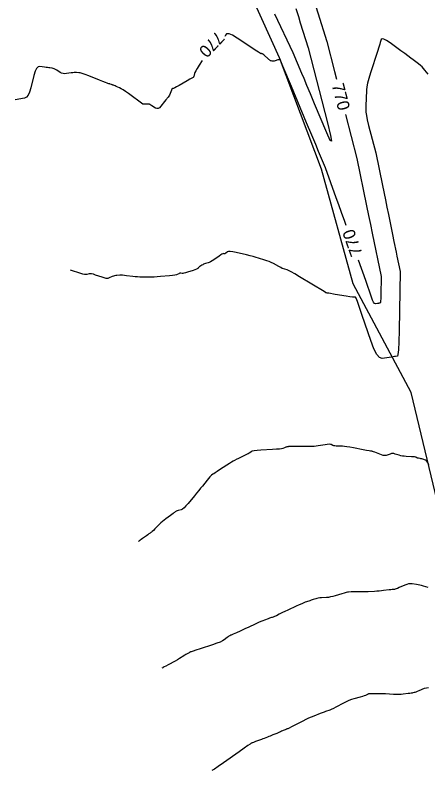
# Model space of a CAD drawing. Extents: x -26 to 1809989, y -25 to 828749.
# Drawn here: x 1809613.3 to 1809781.9, y 827895.2 to 828203.8 of the extents above; entities that cross this region are included whole.
import ezdxf

# ---------------------------------------------------------------- set-up
doc = ezdxf.new("R2010")
doc.units = 0
for name, color, linetype in [('DESIGN - CONTOURS - Index with Text', 7, 'Continuous'), ('DESIGN - CONTOURS - Intermediate with optional Text', 7, 'Continuous'), ('DESIGN - ROW - Slope Lines', 7, 'Continuous')]:
    doc.layers.add(name, color=color, linetype=linetype)

msp = doc.modelspace()

# ---------------------------------------------------------------- linework, layer by layer
at = {"layer": 'DESIGN - CONTOURS - Index with Text'}
for points in [[(1809713.76, 828272.72), (1809725.07, 828242.14), (1809725.84, 828240.05), (1809740.59, 828192.97), (1809743.73, 828180.77), (1809744.54, 828177.64)], [(1809748.49, 828117.8), (1809747.93, 828119.38), (1809746.61, 828123.04), (1809745.45, 828126.28), (1809744.44, 828129.11), (1809740.05, 828141.34), (1809737.23, 828148.11), (1809736.07, 828150.88), (1809734.44, 828154.77), (1809732.35, 828159.77), (1809726.16, 828174.61), (1809722.67, 828182.95), (1809721.8, 828185.04), (1809721.51, 828185.73), (1809721.51, 828185.73), (1809721.45, 828185.72), (1809721.01, 828185.58), (1809720.63, 828185.47), (1809719.45, 828185.11), (1809719.05, 828185), (1809718.72, 828184.93), (1809718.46, 828184.91), (1809718.27, 828184.93), (1809717.87, 828185.05), (1809717.74, 828185.09), (1809717.65, 828185.12), (1809717.59, 828185.14), (1809717.57, 828185.15), (1809717.57, 828185.15), (1809717.57, 828185.15), (1809717.57, 828185.15), (1809717.57, 828185.15), (1809717.57, 828185.15), (1809715.26, 828187.13), (1809714.82, 828187.51), (1809714.5, 828187.79), (1809714.28, 828187.96), (1809714.18, 828188.04), (1809714.05, 828188.1), (1809714.01, 828188.12), (1809713.96, 828188.12), (1809713.92, 828188.11), (1809713.88, 828188.08), (1809713.78, 828187.99), (1809713.48, 828188.13), (1809712.67, 828188.63), (1809711.35, 828189.5), (1809709.51, 828190.71), (1809703.93, 828194.44), (1809702.06, 828195.57), (1809700.64, 828196.14), (1809699.67, 828196.17), (1809699.15, 828195.64), (1809698.92, 828195.01)], [(1809689.69, 828185.29), (1809688.52, 828183.39), (1809687.69, 828182.04), (1809687.09, 828181.01), (1809686.71, 828180.3), (1809686.55, 828179.91), (1809686.42, 828179.28), (1809686.38, 828179.07), (1809686.34, 828178.91), (1809686.31, 828178.81), (1809686.29, 828178.75), (1809686.24, 828178.68), (1809686.22, 828178.65), (1809686.2, 828178.62), (1809686.16, 828178.55), (1809686.11, 828178.46), (1809685.94, 828178.34), (1809685.47, 828178.05), (1809684.69, 828177.6), (1809683.61, 828176.97), (1809680.33, 828175.08), (1809679.24, 828174.47), (1809678.45, 828174.04), (1809677.95, 828173.81), (1809677.75, 828173.77), (1809677.59, 828173.91), (1809677.52, 828173.9), (1809677.42, 828173.77), (1809677.3, 828173.52), (1809677.14, 828173.15), (1809676.37, 828171.14), (1809675.74, 828170.26), (1809675.66, 828170.15), (1809675.6, 828170.08), (1809675.57, 828170.04), (1809675.5, 828169.98), (1809675.41, 828169.87), (1809675.18, 828169.59), (1809674.82, 828169.12), (1809674.32, 828168.48), (1809672.8, 828166.55), (1809672.23, 828165.95), (1809671.67, 828165.63), (1809671.12, 828165.57), (1809670.57, 828165.78), (1809669.13, 828166.7), (1809668.65, 828167), (1809668.31, 828167.21), (1809668.1, 828167.33), (1809668.03, 828167.36), (1809668, 828167.34), (1809667.94, 828167.33), (1809667.8, 828167.33), (1809667.58, 828167.33), (1809667.27, 828167.34), (1809666.33, 828167.37), (1809666.02, 828167.38), (1809665.8, 828167.39), (1809665.66, 828167.39), (1809665.62, 828167.39), (1809665.62, 828167.39), (1809665.62, 828167.39), (1809665.62, 828167.39), (1809665.62, 828167.39), (1809665.61, 828167.39), (1809665.6, 828167.4), (1809665.59, 828167.4), (1809665.57, 828167.41), (1809665.47, 828167.44), (1809659.52, 828171.74), (1809658.34, 828172.57), (1809657.35, 828173.23), (1809656.54, 828173.72), (1809655.93, 828174.04), (1809654.55, 828174.65), (1809654.09, 828174.85), (1809653.73, 828175.01), (1809653.5, 828175.11), (1809653.37, 828175.15), (1809653.19, 828175.21), (1809653.1, 828175.23), (1809652.98, 828175.27), (1809652.64, 828175.39), (1809652.1, 828175.57), (1809651.91, 828175.64), (1809651.74, 828175.69), (1809651.6, 828175.74), (1809651.19, 828175.89), (1809650.89, 828176), (1809650.21, 828176.26), (1809649.15, 828176.68), (1809647.71, 828177.24), (1809643.34, 828178.95), (1809641.87, 828179.51), (1809640.71, 828179.92), (1809639.86, 828180.17), (1809639.34, 828180.26), (1809638.36, 828180.3), (1809637.94, 828180.3), (1809637.44, 828180.28), (1809636.84, 828180.22), (1809636.15, 828180.14), (1809634.2, 828179.89), (1809633.49, 828179.85), (1809632.83, 828179.92), (1809632.22, 828180.09), (1809631.66, 828180.38), (1809630.24, 828181.28), (1809629.72, 828181.58), (1809629.25, 828181.81), (1809628.81, 828181.98), (1809628.41, 828182.07), (1809627.39, 828182.21), (1809626.97, 828182.27), (1809626.47, 828182.34), (1809625.88, 828182.43), (1809625.21, 828182.52), (1809623.31, 828182.8), (1809622.63, 828182.65), (1809622, 828181.99), (1809621.44, 828180.82), (1809620.94, 828179.15), (1809619.67, 828174.01), (1809619.15, 828172.31), (1809618.55, 828171.05), (1809617.86, 828170.23), (1809617.08, 828169.86), (1809613.26, 828169.15)], [(1809748.29, 828163.12), (1809752.91, 828145.24), (1809756.86, 828125.9), (1809757.68, 828121.89), (1809758.45, 828118.14), (1809759.16, 828114.65), (1809762.78, 828096.99), (1809762.66, 828089.36), (1809762.63, 828087.93), (1809762.58, 828086.9), (1809762.51, 828086.28), (1809762.43, 828086.07), (1809762.2, 828086.03), (1809762.08, 828086.02), (1809761.9, 828085.99), (1809761.66, 828085.95), (1809761.36, 828085.91), (1809760.48, 828085.77), (1809760.13, 828085.9), (1809759.74, 828086.42), (1809759.31, 828087.3), (1809758.84, 828088.56), (1809756.56, 828095.33), (1809753.56, 828103.68)]]:
    msp.add_lwpolyline(points, dxfattribs=at)
at = {"layer": 'DESIGN - CONTOURS - Intermediate with optional Text'}
for points in [[(1809727.99, 828206.44), (1809728.99, 828203.25), (1809729.78, 828200.71), (1809733.01, 828190.39), (1809740.9, 828159.81), (1809742.14, 828154.63), (1809742.5, 828152.21), (1809741.97, 828152.54), (1809740.56, 828155.62), (1809735.6, 828167.51), (1809733.88, 828171.64), (1809732.44, 828175.09), (1809731.28, 828177.88), (1809730.39, 828180), (1809726.91, 828188.32), (1809719.36, 828204.13)], [(1809782, 828179.64), (1809780.69, 828181.35), (1809780.15, 828181.99), (1809779.53, 828182.63), (1809778.83, 828183.26), (1809778.04, 828183.89), (1809775.83, 828185.56), (1809774.9, 828186.26), (1809773.76, 828187.11), (1809772.42, 828188.1), (1809770.87, 828189.23), (1809766.47, 828192.45), (1809765.01, 828193.44), (1809763.92, 828194.02), (1809763.2, 828194.17), (1809762.86, 828193.9), (1809762.44, 828192.63), (1809762.2, 828191.9), (1809761.81, 828190.68), (1809761.26, 828188.96), (1809758.45, 828180.18), (1809757.75, 828177.9), (1809757.25, 828175.98), (1809756.93, 828174.44), (1809756.79, 828173.25), (1809756.66, 828169.61), (1809756.62, 828168.7), (1809756.59, 828167.85), (1809756.56, 828167.06), (1809756.49, 828165.04), (1809756.55, 828164.08), (1809756.76, 828162.71), (1809757.14, 828160.93), (1809757.68, 828158.73), (1809760.57, 828147.56), (1809763.32, 828134.15), (1809764.52, 828128.31), (1809765.13, 828125.31), (1809765.75, 828122.27), (1809767.43, 828114.1), (1809768.01, 828111.25), (1809768.91, 828106.85), (1809769.23, 828105.3), (1809770.51, 828099.05), (1809770.13, 828074.84), (1809770.03, 828070.29), (1809769.87, 828067.03), (1809769.67, 828065.06), (1809769.42, 828064.38), (1809768.67, 828064.28), (1809768.3, 828064.23), (1809767.73, 828064.14), (1809766.01, 828063.88), (1809763.2, 828063.44), (1809762.12, 828063.77), (1809760.98, 828065.11), (1809759.78, 828067.43), (1809758.52, 828070.76), (1809755.08, 828080.95), (1809753.94, 828084.29), (1809753.1, 828086.67), (1809752.56, 828088.08), (1809752.31, 828088.52), (1809752.05, 828088.43), (1809751.75, 828088.43), (1809751.06, 828088.51), (1809749.96, 828088.67), (1809748.47, 828088.91), (1809743.96, 828089.65), (1809741.4, 828090.07), (1809740.74, 828090.17), (1809740.5, 828090.21), (1809740.4, 828090.22), (1809740.36, 828090.24), (1809740.29, 828090.27), (1809740.19, 828090.32), (1809740.08, 828090.4), (1809739.49, 828090.77), (1809729.43, 828096.87), (1809727.49, 828098.03), (1809726.01, 828098.88), (1809724.97, 828099.42), (1809724.38, 828099.66), (1809723.39, 828099.9), (1809722.96, 828100.03), (1809722.42, 828100.25), (1809721.76, 828100.57), (1809720.99, 828100.98), (1809718.76, 828102.19), (1809717.92, 828102.62), (1809717.05, 828103.01), (1809716.15, 828103.37), (1809715.23, 828103.68), (1809712.74, 828104.46), (1809711.73, 828104.76), (1809710.56, 828105.08), (1809709.24, 828105.42), (1809707.76, 828105.77), (1809703.62, 828106.72), (1809702.23, 828107.01), (1809701.17, 828107.16), (1809700.43, 828107.17), (1809700.01, 828107.04), (1809699.34, 828106.5), (1809699.1, 828106.33), (1809698.9, 828106.22), (1809698.74, 828106.17), (1809698.62, 828106.18), (1809698.33, 828106.29), (1809698.14, 828106.26), (1809697.78, 828106.08), (1809697.25, 828105.75), (1809696.56, 828105.27), (1809694.49, 828103.78), (1809693.76, 828103.28), (1809693.12, 828102.9), (1809692.58, 828102.63), (1809692.12, 828102.47), (1809691.01, 828102.19), (1809690.62, 828102.08), (1809690.24, 828101.94), (1809689.9, 828101.77), (1809689.59, 828101.57), (1809688.79, 828101.02), (1809688.52, 828100.83), (1809688.31, 828100.67), (1809688.15, 828100.53), (1809688.05, 828100.43), (1809687.85, 828100.18), (1809687.68, 828100.06), (1809687.3, 828099.9), (1809686.73, 828099.69), (1809685.95, 828099.43), (1809683.62, 828098.67), (1809682.83, 828098.42), (1809682.21, 828098.26), (1809681.76, 828098.17), (1809681.48, 828098.16), (1809680.96, 828098.25), (1809680.76, 828098.26), (1809680.55, 828098.24), (1809680.33, 828098.18), (1809680.11, 828098.08), (1809679.51, 828097.78), (1809679.14, 828097.66), (1809678.48, 828097.54), (1809677.53, 828097.4), (1809676.29, 828097.26), (1809672.6, 828096.88), (1809671.27, 828096.76), (1809670.03, 828096.67), (1809668.89, 828096.63), (1809667.85, 828096.63), (1809665.19, 828096.68), (1809664.2, 828096.71), (1809663.22, 828096.76), (1809662.25, 828096.84), (1809661.3, 828096.95), (1809658.77, 828097.27), (1809657.88, 828097.37), (1809657.12, 828097.43), (1809656.49, 828097.46), (1809655.98, 828097.45), (1809654.79, 828097.37), (1809654.34, 828097.32), (1809653.88, 828097.22), (1809653.42, 828097.08), (1809652.95, 828096.89), (1809651.68, 828096.33), (1809651.14, 828096.19), (1809650.47, 828096.19), (1809649.68, 828096.33), (1809648.77, 828096.61), (1809646.16, 828097.55), (1809645.26, 828097.85), (1809644.51, 828098.03), (1809643.93, 828098.09), (1809643.5, 828098.05), (1809642.56, 828097.77), (1809642.15, 828097.72), (1809641.59, 828097.77), (1809640.9, 828097.92), (1809640.08, 828098.17), (1809635.92, 828099.58)], [(1809782.27, 828019.94), (1809781.81, 828020.91), (1809781.36, 828021.55), (1809780.93, 828021.85), (1809779.79, 828022.24), (1809779.39, 828022.36), (1809779.05, 828022.46), (1809778.77, 828022.53), (1809778.55, 828022.57), (1809778.04, 828022.64), (1809777.86, 828022.67), (1809777.69, 828022.72), (1809777.54, 828022.77), (1809777.4, 828022.84), (1809777.06, 828023.03), (1809776.84, 828023.1), (1809776.46, 828023.16), (1809775.9, 828023.21), (1809775.18, 828023.26), (1809773.01, 828023.38), (1809772.23, 828023.44), (1809771.49, 828023.54), (1809770.82, 828023.68), (1809770.19, 828023.85), (1809768.59, 828024.37), (1809768.01, 828024.52), (1809767.47, 828024.57), (1809766.97, 828024.52), (1809766.5, 828024.37), (1809765.32, 828023.85), (1809764.84, 828023.71), (1809764.27, 828023.7), (1809763.63, 828023.82), (1809762.91, 828024.06), (1809760.88, 828024.86), (1809760.2, 828025.12), (1809759.68, 828025.32), (1809759.32, 828025.44), (1809759.12, 828025.48), (1809758.79, 828025.51), (1809758.5, 828025.56), (1809757.85, 828025.67), (1809756.86, 828025.86), (1809755.51, 828026.12), (1809751.47, 828026.91), (1809750.05, 828027.17), (1809748.83, 828027.37), (1809747.8, 828027.49), (1809746.98, 828027.54), (1809745.04, 828027.59), (1809744.37, 828027.62), (1809743.83, 828027.68), (1809743.4, 828027.77), (1809743.09, 828027.88), (1809742.42, 828028.22), (1809742.07, 828028.31), (1809741.53, 828028.33), (1809740.79, 828028.28), (1809739.86, 828028.15), (1809737.12, 828027.73), (1809736.2, 828027.59), (1809735.48, 828027.49), (1809734.96, 828027.43), (1809734.64, 828027.41), (1809733.78, 828027.41), (1809733.32, 828027.41), (1809732.7, 828027.41), (1809731.91, 828027.42), (1809729.6, 828027.43), (1809728.1, 828027.44), (1809727.52, 828027.44), (1809727.05, 828027.44), (1809725.97, 828027.45), (1809725.59, 828027.45), (1809725.27, 828027.43), (1809725, 828027.4), (1809724.78, 828027.37), (1809724.26, 828027.25), (1809724.06, 828027.2), (1809723.84, 828027.13), (1809723.59, 828027.04), (1809723.33, 828026.94), (1809722.59, 828026.64), (1809722.13, 828026.52), (1809721.28, 828026.41), (1809720.06, 828026.3), (1809718.46, 828026.18), (1809713.69, 828025.89), (1809712.1, 828025.77), (1809710.9, 828025.63), (1809710.1, 828025.49), (1809709.69, 828025.33), (1809709.13, 828024.88), (1809708.88, 828024.7), (1809708.52, 828024.49), (1809708.05, 828024.25), (1809707.49, 828023.98), (1809705.86, 828023.21), (1809705.28, 828022.94), (1809704.75, 828022.69), (1809704.27, 828022.46), (1809703.86, 828022.26), (1809702.82, 828021.75), (1809702.34, 828021.48), (1809701.67, 828021.08), (1809700.82, 828020.54), (1809699.78, 828019.86), (1809696.77, 828017.86), (1809695.75, 828017.19), (1809694.97, 828016.67), (1809694.41, 828016.29), (1809694.08, 828016.07), (1809693.52, 828015.68), (1809693.24, 828015.44), (1809692.84, 828015.02), (1809692.32, 828014.42), (1809691.68, 828013.63), (1809689.79, 828011.29), (1809689.05, 828010.38), (1809688.26, 828009.4), (1809687.4, 828008.36), (1809686.48, 828007.24), (1809683.94, 828004.18), (1809683.05, 828003.16), (1809682.28, 828002.39), (1809681.64, 828001.87), (1809681.11, 828001.6), (1809679.87, 828001.22), (1809679.45, 828001.09), (1809679.11, 828000.96), (1809678.86, 828000.83), (1809678.69, 828000.72), (1809678.34, 828000.42), (1809678.14, 828000.26), (1809677.8, 828000), (1809677.32, 827999.65), (1809676.7, 827999.2), (1809674.86, 827997.87), (1809674.17, 827997.35), (1809673.49, 827996.79), (1809672.82, 827996.18), (1809672.15, 827995.53), (1809670.37, 827993.74), (1809669.77, 827993.15), (1809669.31, 827992.7), (1809668.97, 827992.4), (1809668.77, 827992.24), (1809668.42, 827992.02), (1809668.22, 827991.9), (1809667.91, 827991.68), (1809667.49, 827991.37), (1809666.94, 827990.97), (1809665.34, 827989.78), (1809664.8, 827989.38), (1809664.39, 827989.09), (1809664.12, 827988.9), (1809663.97, 827988.82), (1809663.6, 827988.65)], [(1809781.95, 827969.79), (1809780.06, 827970.36), (1809779.35, 827970.56), (1809778.66, 827970.73), (1809777.96, 827970.88), (1809777.28, 827971), (1809775.46, 827971.29), (1809774.76, 827971.34), (1809774.02, 827971.27), (1809773.24, 827971.07), (1809772.43, 827970.76), (1809770.2, 827969.76), (1809769.45, 827969.44), (1809768.88, 827969.2), (1809768.49, 827969.06), (1809768.28, 827969.02), (1809767.96, 827969.01), (1809767.75, 827969), (1809767.35, 827968.96), (1809766.77, 827968.9), (1809766.01, 827968.81), (1809763.74, 827968.53), (1809762.88, 827968.43), (1809761.99, 827968.35), (1809761.06, 827968.28), (1809760.12, 827968.22), (1809757.55, 827968.08), (1809756.63, 827968.03), (1809755.78, 827968), (1809755.01, 827967.99), (1809754.3, 827968), (1809752.54, 827968.03), (1809751.91, 827968.03), (1809751.36, 827968.03), (1809750.89, 827968.02), (1809750.49, 827968), (1809749.52, 827967.93), (1809749.08, 827967.86), (1809748.47, 827967.73), (1809747.7, 827967.52), (1809746.77, 827967.25), (1809744.07, 827966.41), (1809743.08, 827966.13), (1809742.16, 827965.92), (1809741.29, 827965.78), (1809740.49, 827965.7), (1809738.42, 827965.57), (1809737.69, 827965.52), (1809737.06, 827965.44), (1809736.52, 827965.34), (1809736.09, 827965.22), (1809735.06, 827964.86), (1809734.66, 827964.72), (1809734.21, 827964.57), (1809733.73, 827964.41), (1809733.22, 827964.23), (1809731.79, 827963.74), (1809731.16, 827963.51), (1809730.33, 827963.17), (1809729.32, 827962.72), (1809728.11, 827962.17), (1809724.64, 827960.57), (1809723.45, 827960.02), (1809722.47, 827959.55), (1809721.71, 827959.18), (1809721.17, 827958.9), (1809720, 827958.27), (1809719.6, 827958.06), (1809719.25, 827957.89), (1809718.97, 827957.77), (1809718.75, 827957.7), (1809718.24, 827957.56), (1809718, 827957.48), (1809717.66, 827957.37), (1809717.23, 827957.22), (1809716.69, 827957.03), (1809715.14, 827956.46), (1809714.48, 827956.2), (1809713.67, 827955.87), (1809712.72, 827955.44), (1809711.61, 827954.94), (1809708.45, 827953.48), (1809707.39, 827953), (1809706.57, 827952.62), (1809706, 827952.35), (1809705.68, 827952.2), (1809705.15, 827951.94), (1809704.91, 827951.83), (1809704.6, 827951.69), (1809704.2, 827951.51), (1809703.73, 827951.31), (1809702.37, 827950.72), (1809701.56, 827950.37), (1809701.32, 827950.26), (1809701.18, 827950.2), (1809700.95, 827950.1), (1809700.82, 827950.02), (1809700.59, 827949.86), (1809700.27, 827949.62), (1809699.86, 827949.3), (1809698.62, 827948.35), (1809697.98, 827947.96), (1809696.98, 827947.5), (1809695.61, 827946.98), (1809693.89, 827946.39), (1809688.81, 827944.73), (1809687.14, 827944.18), (1809685.94, 827943.79), (1809685.2, 827943.54), (1809684.93, 827943.45), (1809684.82, 827943.39), (1809684.76, 827943.36), (1809684.66, 827943.31), (1809684.52, 827943.24), (1809684.35, 827943.14), (1809683.83, 827942.86), (1809683.61, 827942.74), (1809683.33, 827942.57), (1809683.01, 827942.37), (1809682.62, 827942.13), (1809681.54, 827941.42), (1809681.05, 827941.12), (1809680.4, 827940.74), (1809679.59, 827940.28), (1809678.61, 827939.74), (1809675.8, 827938.21), (1809674.87, 827937.7), (1809674.19, 827937.33), (1809673.75, 827937.1), (1809673.56, 827937), (1809673.26, 827936.87)], [(1809782.2, 827928.72), (1809781.27, 827928.68), (1809780.42, 827928.45), (1809778.25, 827927.58), (1809777.52, 827927.29), (1809776.94, 827927.07), (1809776.52, 827926.92), (1809776.25, 827926.84), (1809775.75, 827926.71), (1809775.49, 827926.65), (1809775.09, 827926.59), (1809774.55, 827926.51), (1809773.86, 827926.42), (1809771.85, 827926.16), (1809771.03, 827926.09), (1809770.09, 827926.05), (1809769.03, 827926.06), (1809767.85, 827926.1), (1809764.53, 827926.28), (1809763.36, 827926.34), (1809762.34, 827926.38), (1809761.47, 827926.39), (1809760.75, 827926.39), (1809759.04, 827926.36), (1809758.47, 827926.35), (1809758.06, 827926.34), (1809757.8, 827926.33), (1809757.7, 827926.32), (1809757.63, 827926.29), (1809757.59, 827926.26), (1809757.49, 827926.22), (1809757.36, 827926.15), (1809757.18, 827926.05), (1809756.65, 827925.76), (1809756.35, 827925.63), (1809755.86, 827925.46), (1809755.16, 827925.25), (1809754.27, 827925), (1809751.63, 827924.27), (1809750.62, 827923.95), (1809749.57, 827923.55), (1809748.49, 827923.07), (1809747.37, 827922.51), (1809744.32, 827920.91), (1809743.28, 827920.37), (1809742.44, 827919.96), (1809741.81, 827919.67), (1809741.37, 827919.5), (1809740.47, 827919.23), (1809740.06, 827919.09), (1809739.48, 827918.88), (1809738.75, 827918.6), (1809737.86, 827918.26), (1809735.28, 827917.24), (1809734.26, 827916.82), (1809733.17, 827916.33), (1809732, 827915.77), (1809730.74, 827915.14), (1809727.27, 827913.36), (1809726.12, 827912.78), (1809725.27, 827912.35), (1809724.71, 827912.08), (1809724.46, 827911.98), (1809724.17, 827911.9), (1809724.02, 827911.86), (1809723.81, 827911.77), (1809723.53, 827911.65), (1809723.17, 827911.49), (1809722.13, 827911), (1809721.72, 827910.81), (1809721.25, 827910.61), (1809720.73, 827910.39), (1809720.16, 827910.16), (1809718.58, 827909.52), (1809718, 827909.28), (1809717.43, 827909.05), (1809716.88, 827908.83), (1809716.34, 827908.62), (1809714.94, 827908.07), (1809714.43, 827907.87), (1809713.94, 827907.68), (1809713.48, 827907.51), (1809713.05, 827907.34), (1809711.93, 827906.93), (1809711.53, 827906.78), (1809711.2, 827906.65), (1809710.91, 827906.55), (1809710.68, 827906.46), (1809710.14, 827906.25), (1809709.96, 827906.19), (1809709.82, 827906.13), (1809709.73, 827906.1), (1809709.67, 827906.07), (1809709.59, 827906.04), (1809709.26, 827905.82), (1809708.35, 827905.18), (1809706.84, 827904.12), (1809704.74, 827902.65), (1809698.37, 827898.16), (1809696.25, 827896.68), (1809694.68, 827895.6), (1809693.66, 827894.92)]]:
    msp.add_lwpolyline(points, dxfattribs=at)
at = {"layer": 'DESIGN - ROW - Slope Lines'}
for p, q in [((1809721.26, 828186.4), (1809701.14, 828230.72)), ((1809738.44, 828140.85), (1809721.26, 828186.4)), ((1809751.3, 828093.92), (1809738.44, 828140.85)), ((1809775.06, 828049.5), (1809751.3, 828093.92)), ((1809786.54, 828001.77), (1809775.06, 828049.5))]:
    msp.add_line(p, q, dxfattribs=at)

# ---------------------------------------------------------------- texts
at = {"layer": 'DESIGN - CONTOURS - Index with Text'}
for rotation, p in [(226.5224, (1809695.64, 828197.54)), (284.4807, (1809742.58, 828175.23)), (109.7406, (1809755.29, 828106.26))]:
    msp.add_text('770', height=5, rotation=rotation, dxfattribs=at).set_placement(p)

doc.saveas('drawing.dxf')
